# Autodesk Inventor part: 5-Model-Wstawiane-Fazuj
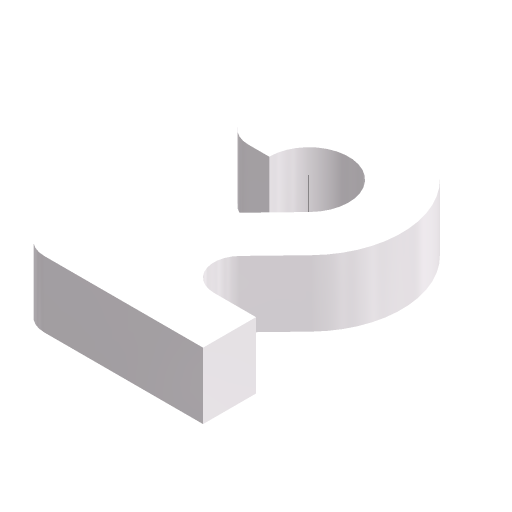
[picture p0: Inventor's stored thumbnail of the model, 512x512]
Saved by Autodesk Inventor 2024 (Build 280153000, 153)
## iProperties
Company: ATC
Shininess: 21.0
Length Units: 11269
Angle Units: 11279
Time Units: 11290
Mass Units: 11283
Length Display Precision: 3
Angle Display Precision: 2
Compacted: True
Created: 2023-03
Part Number: 5-Model-Wstawiane-Fazuj
Document SubType Name: Modeling
Designer: Andrzej Jaskulski
Material: Kurs-AJ
Density: 1 g/cm^3
Appearance: Kurs-AJ
Checked By: A.J.
Engr Approved By: Andrzej Jaskulski
Mfg Approved By: Andrzej Jaskulski
Authority: A.J.
Density: 0.0
Volumn: 0.0
Area: 0.0
PropertySet Name: Model Information
Control State: 0
Master: False
Checked Out: False
Title: A.J.: Kurs R2024-MEP
Author: Andrzej Jaskulski
Revision Number: 1/24
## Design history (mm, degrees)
sketch "Zarys dwójki"
  geometry: L1 (140, 0.063)-(0, 0.063) reference; L2 (0, 0.063)-(0, 34.389) reference; L3 (0, 150.063)-(40, 150.063); L4 (140, 0.063)-(140, 40.063); L5 (140, 40.063)-(61.086, 40.063); L6 (61.086, 40.063)-(120.354, 101.437); L7 (91.58, 129.223)-(0, 34.389); A1 r 30 centre (70, 150.063) between (91.58, 129.223) and (40, 150.063); A2 r 70 centre (70, 150.063) between (120.354, 101.437) and (0, 150.063)
  constraints: 14 end point, 4 perpendicular, 4 point on circle, 2 centre point, 2 parallel, 2 tangent, 1 coincident
  dimensions: "d0" = 140 distance of L1.start L1.end; "d1" = 150 vertical distance of A1.centre L1.end; "d2" = 70 horizontal distance of L1.end A1.centre; "d3" = 46 deg angle of L6 L5; "d4" = 150 distance of L3.start L1.end (= d1); "d5" = 30 radius of A1; "d6" = 70 radius of A2
extrude "Dwójka" new body sketch "Zarys dwójki" distance "d7" = 50; taper "d8" = 0 deg
node "Oś walca"
fillet "Zaokrąglenie 3 x R30" dims "d12" = 20
node "Bryła1"
node "Korpusy bryłowe"
node "Korpusy powierzchniowe"
other parameters: "d9" = 90 deg
